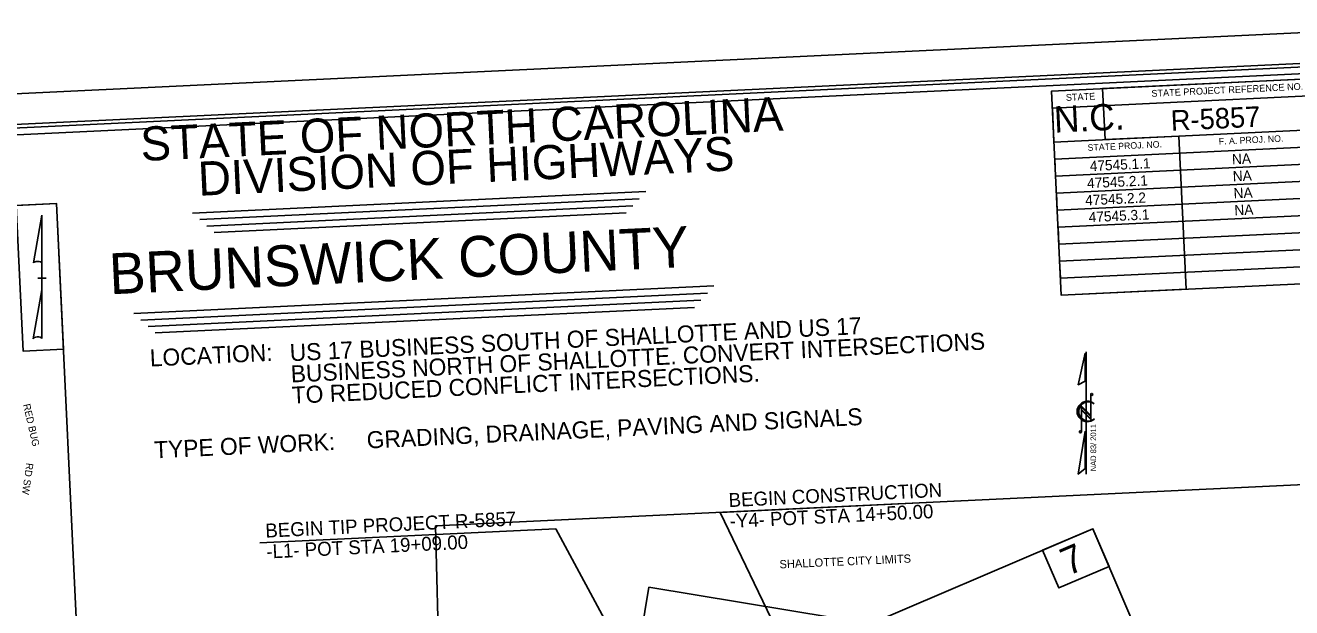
# Model space of a CAD drawing. Extents: x 2170913 to 2188101, y 74009 to 87693.
# Drawn here: x 2175486 to 2182226, y 79461 to 82562 of the extents above; entities that cross this region are included whole.
import ezdxf

# ---------------------------------------------------------------- set-up
doc = ezdxf.new("R2010")
doc.units = 0
for name, color, linetype in [('CTL Primary Horizontal and Vertical CELL', 7, 'Continuous'), ('CTL Primary Horizontal and Vertical Cogo Comment', 7, 'Continuous'), ('CTL Primary Horizontal and Vertical Cogo Elevation', 7, 'Continuous'), ('CTL Primary Horizontal Cogo Comment', 7, 'Continuous'), ('CTL Primary Horizontal Cogo Number', 7, 'Continuous'), ('Exist Other Culture Sign Cogo Point CELL', 7, 'Continuous'), ('Exist Property Iron Pin CELL', 7, 'Continuous'), ('Exist Property Iron Pin Cogo Elevation', 7, 'Continuous'), ('Exist Right of Way Monument CELL', 7, 'Continuous'), ('Exist Structure Minor Pipes HDPE 30 Inch', 7, 'Continuous'), ('Exist Structure Minor Pipes RCP 15 Inch', 7, 'Continuous')]:
    doc.layers.add(name, color=color, linetype=linetype)

msp = doc.modelspace()

# ---------------------------------------------------------------- linework, layer by layer
at = {"layer": 'CTL Primary Horizontal and Vertical CELL'}
msp.add_lwpolyline([(2183118, 82562.2), (2170912.8, 81981.8), (2171291.9, 74009.3), (2183497.2, 74589.8)], close=True, dxfattribs=at)
at = {"layer": 'CTL Primary Horizontal and Vertical Cogo Comment'}
for p, q in [((2175528.9, 81296.8), (2175574, 81551.4)), ((2175574.3, 81551.4), (2175574, 81551.4)), ((2175574.3, 81551.4), (2175574, 81551.4)), ((2175574.3, 81551.4), (2175574.2, 81288.8)), ((2175574.2, 81152.6), (2175574.2, 81296.5)), ((2175574.2, 81288.8), (2175574.2, 81296.3)), ((2175552.2, 81216.4), (2175551.9, 81216.4)), ((2175571.7, 81216.4), (2175552.2, 81216.4)), ((2175552.5, 81216.4), (2175596.4, 81216.3)), ((2175574.2, 81152.6), (2175528.2, 80893.2)), ((2175574.3, 80894.2), (2175574.2, 81152.6))]:
    msp.add_line(p, q, dxfattribs=at)
for centre, start_param, end_param in [((2175551.6, 81294.1), 0.216388, 2.908219), ((2175551.5, 80892.2), 0.201328, 3.141593)]:
    msp.add_ellipse(centre, major_axis=(23.2, -0.2), ratio=0.461098, start_param=start_param, end_param=end_param, dxfattribs=at)
at = {"layer": 'CTL Primary Horizontal and Vertical Cogo Elevation'}
for points in [[(2172704.4, 81472.7), (2175652.3, 81612.9), (2175771.5, 79107.1), (2172823.6, 78966.9)], [(2175652.3, 81612.9), (2175437.7, 81602.7), (2175474.6, 80826.6), (2175689.2, 80836.8)]]:
    msp.add_lwpolyline(points, close=True, dxfattribs=at)
at = {"layer": 'CTL Primary Horizontal Cogo Comment'}
msp.add_lwpolyline([(2171378.4, 74176.5), (2183456.8, 74750.8), (2183093.1, 82397.9), (2171014.8, 81823.6)], close=True, dxfattribs=at)
at = {"layer": 'CTL Primary Horizontal Cogo Number'}
for p, q in [((2176376.5, 81562.1), (2178788.2, 81676.8)), ((2176414.5, 81527.6), (2178753.7, 81638.8)), ((2176452.4, 81493), (2178719.2, 81600.9)), ((2176490.4, 81458.5), (2178684.7, 81562.9)), ((2176063.1, 81027.1), (2179150.6, 81173.9)), ((2176101, 80992.6), (2179116.1, 81135.9)), ((2176139, 80958), (2179081.6, 81098)), ((2176177, 80923.6), (2179047.1, 81060))]:
    msp.add_line(p, q, dxfattribs=at)
for points in [[(2182931, 82371.7), (2172204.2, 81861.7)], [(2182896.4, 82333.7), (2172604.7, 81844.3)], [(2182941.3, 82306.9), (2180948.2, 82212), (2180999.9, 81125), (2181664.1, 81156.5), (2181625.3, 81971.8), (2181232.9, 81953.2), (2181220, 82225.1), (2182397.8, 82281)], [(2182954.2, 82035.1), (2180961.1, 81940.3), (2180952.5, 82121.5), (2182945.6, 82216.3)], [(2182962.8, 81853.8), (2180969.7, 81759.1), (2180965.4, 81849.6), (2182958.5, 81944.4)], [(2182971.5, 81672.7), (2180978.3, 81577.9), (2180974, 81668.5), (2182967.1, 81763.3)], [(2182980.1, 81491.4), (2180987, 81396.7), (2180982.6, 81487.4), (2182975.8, 81582.1)], [(2182988.7, 81310.3), (2180995.6, 81215.6), (2180991.3, 81306.1), (2182984.4, 81400.9)], [(2180999.9, 81125), (2182993, 81219.7)]]:
    msp.add_lwpolyline(points, dxfattribs=at)
at = {"layer": 'Exist Property Iron Pin CELL'}
for p, q in [((2180464.8, 80029), (2179184.6, 79968.1)), ((2179603.8, 79096.1), (2179184.6, 79968.1)), ((2178309.2, 79881.2), (2176733.7, 79806.3)), ((2178765.7, 79032.9), (2178309.2, 79881.2))]:
    msp.add_line(p, q, dxfattribs=at)
at = {"layer": 'Exist Property Iron Pin Cogo Elevation'}
for p, q in [((2181132, 80172.6), (2181132, 80822.6)), ((2181156.5, 80596.4), (2181156.5, 80463)), ((2181156.5, 80483.8), (2181106.8, 80533.5)), ((2181106.8, 80533.5), (2181106.8, 80397.9)), ((2181156.5, 80478.9), (2181106.8, 80528.6)), ((2181106.8, 80528.6), (2181106.8, 80516.4)), ((2181156.5, 80466.7), (2181106.8, 80516.4)), ((2181106.8, 80516.4), (2181156.5, 80466.7)), ((2181156.5, 80463), (2181106.8, 80512.7)), ((2181174.9, 80546.7), (2181175.6, 80546.2)), ((2181156.5, 80466.7), (2181156.5, 80478.9))]:
    msp.add_line(p, q, dxfattribs=at)
for points in [[(2181127.5, 80816.9), (2181090.4, 80648.1), (2181127.5, 80666.9)], [(2181126.7, 80401.6), (2181089.9, 80172.6), (2181126.7, 80201.6)]]:
    msp.add_lwpolyline(points, close=True, dxfattribs=at)
for centre in [(2181161.8, 80596.3), (2181101.5, 80397.7)]:
    msp.add_circle(centre, 5.3, dxfattribs=at)
for centre, radius, start, end in [((2181138.9, 80505.7), 54.6, 47.84002, 312.39406), ((2181144.2, 80505.7), 51.2, 53.09504, 308.62871)]:
    msp.add_arc(centre, radius, start, end, dxfattribs=at)
at = {"layer": 'Exist Right of Way Monument CELL'}
for points in [[(2179788.7, 79292), (2180201, 78326.3), (2181580.5, 78915.3), (2181168.2, 79881)], [(2181168.2, 79881), (2180900.7, 79766.8), (2180986.4, 79566.1), (2181253.9, 79680.3)], [(2178805.2, 79569.3), (2178633.6, 78533.5), (2180113.4, 78288.3), (2180285.1, 79324.1)]]:
    msp.add_lwpolyline(points, close=True, dxfattribs=at)
at = {"layer": 'Exist Structure Minor Pipes HDPE 30 Inch'}
msp.add_lwpolyline([(2177668.6, 79896.6), (2182629.7, 80132.5), (2182882.8, 78325.4), (2178890.9, 77226), (2178290.9, 78673.1), (2177852.1, 79004.7), (2177687.9, 79128.8)], close=True, dxfattribs=at)

# ---------------------------------------------------------------- texts
at = {"layer": 'CTL Primary Horizontal Cogo Number'}
for s, height, p in [('STATE PROJECT REFERENCE NO.', 36.278, (2181480.6, 82181.1)), ('STATE OF NORTH CAROLINA', 181.398, (2176103.3, 81839.3)), ('STATE', 36.28, (2181025.1, 82159.5)), ('N.C.', 140.4, (2180964.2, 81990.2)), ('DIVISION OF HIGHWAYS', 181.398, (2176409.2, 81654.1)), ('F. A. PROJ. NO.', 34.829, (2181838.9, 81926.5)), ('STATE PROJ. NO.', 34.829, (2181140.9, 81893.3)), ('LOCATION: ', 90.7, (2176150.6, 80744.7)), ('TYPE OF WORK:', 90.7, (2176173.9, 80255.4))]:
    msp.add_text(s, height=height, rotation=2.72267, dxfattribs=at).set_placement(p)
at = {"layer": 'Exist Other Culture Sign Cogo Point CELL'}
for s, height, p in [('R-5857', 108.84, (2181585.1, 82000.4)), ('47545.1.1     ', 54.42, (2181152.8, 81785.6)), ('NA            ', 54.42, (2181909.7, 81821.6)), ('47545.2.1 ', 54.42, (2181138.5, 81694.1)), ('NA            ', 54.42, (2181914, 81731)), ('NA            ', 54.42, (2181918.3, 81640.4)), ('47545.2.2 ', 54.42, (2181128.4, 81602.9)), ('47545.3.1 ', 54.42, (2181147.1, 81513.1)), ('NA            ', 54.42, (2181922.6, 81549.9)), ('BRUNSWICK COUNTY', 217.678, (2175936.9, 81129.4)), ('US 17 BUSINESS SOUTH OF SHALLOTTE AND US 17', 90.7, (2176895.4, 80773.1)), ('BUSINESS NORTH OF SHALLOTTE. CONVERT INTERSECTIONS', 90.7, (2176900.8, 80659.8)), ('TO REDUCED CONFLICT INTERSECTIONS.', 90.7, (2176906.2, 80546.6)), ('GRADING, DRAINAGE, PAVING AND SIGNALS', 90.7, (2177305, 80308.2))]:
    msp.add_text(s, height=height, rotation=2.72267, dxfattribs=at).set_placement(p)
at = {"layer": 'Exist Property Iron Pin CELL'}
for s, height, rotation, p in [('BEGIN CONSTRUCTION', 74.313, 2.80128, (2179231, 79996.1)), ('-Y4- POT STA 14+50.00', 74.313, 2.80128, (2179236.4, 79884.8)), ('BEGIN TIP PROJECT R-5857', 74.313, 2.80128, (2176765.2, 79833.5)), ('-L1- POT STA 19+09.00', 74.313, 2.80128, (2176770.6, 79722.2)), ('SHALLOTTE CITY LIMITS', 44.037, 2.56951, (2179501.3, 79669.6))]:
    msp.add_text(s, height=height, rotation=rotation, dxfattribs=at).set_placement(p)
at = {"layer": 'Exist Property Iron Pin Cogo Elevation'}
msp.add_text('NAD 83/ 2011', height=30, rotation=90, dxfattribs=at).set_placement((2181185.5, 80186.8))
at = {"layer": 'Exist Right of Way Monument CELL'}
msp.add_text('7', height=147.6, rotation=23.12057, dxfattribs=at).set_placement((2181036.3, 79628.8))
at = {"layer": 'Exist Structure Minor Pipes RCP 15 Inch'}
for s, rotation, p in [('RED BUG', 282.92778, (2175473.7, 80541.9)), ('RD SW', 261.94644, (2175491.5, 80233.3))]:
    msp.add_text(s, height=37.96, rotation=rotation, dxfattribs=at).set_placement(p)

doc.saveas('drawing.dxf')
